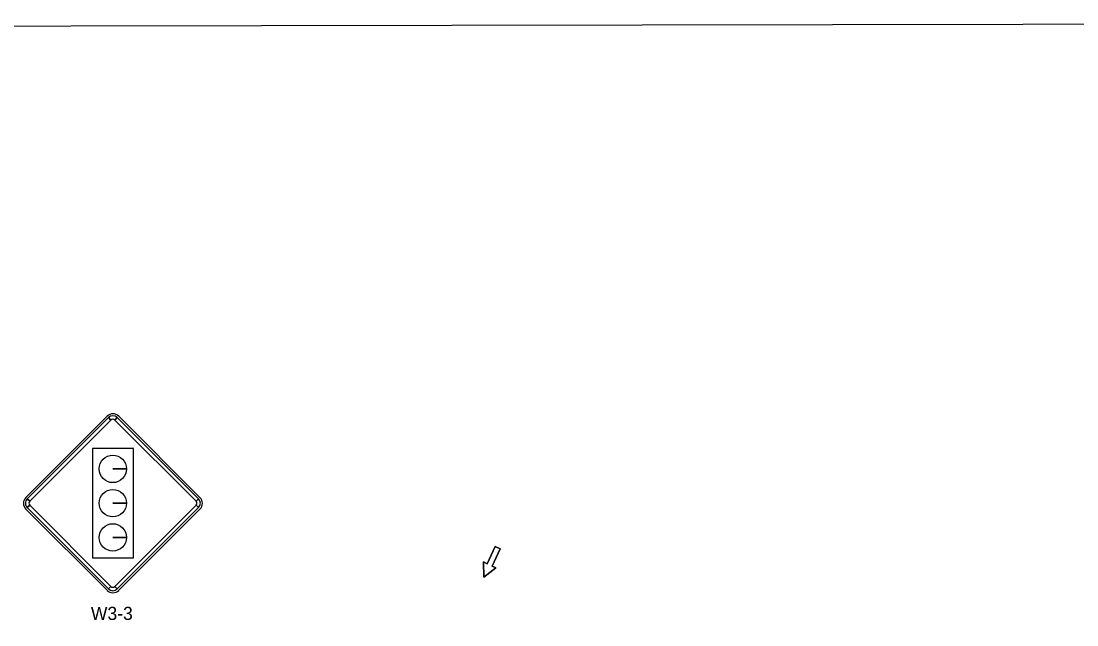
# Model space of a CAD drawing. Extents: x 16513048 to 16518780, y 7009856 to 7010869.
# Drawn here: x 16515285.9 to 16515768.8, y 7010593 to 7010869.1 of the extents above; entities that cross this region are included whole.
import ezdxf

# ---------------------------------------------------------------- set-up
doc = ezdxf.new("R2010")
doc.units = 0
for name, color, linetype in [('dsnStdLabel', 7, 'Continuous'), ('Level 2', 7, 'Continuous'), ('Level 5', 7, 'Continuous'), ('NamedBoundary', 7, 'Continuous')]:
    doc.layers.add(name, color=color, linetype=linetype)

msp = doc.modelspace()

# ---------------------------------------------------------------- linework, layer by layer
at = {"layer": 'dsnStdLabel'}
for p, q in [((16515325.26, 7010688.43), (16515288.08, 7010651.26)), ((16515325.92, 7010687.77), (16515327.03, 7010686.66)), ((16515328.8, 7010686.66), (16515329.91, 7010687.77)), ((16515367.75, 7010651.26), (16515330.57, 7010688.43)), ((16515334.13, 7010664.29), (16515327.87, 7010664.29)), ((16515327.87, 7010664.29), (16515334.13, 7010664.29)), ((16515289.85, 7010649.49), (16515288.75, 7010650.59)), ((16515367.08, 7010650.59), (16515365.98, 7010649.49)), ((16515288.08, 7010645.95), (16515325.26, 7010608.77)), ((16515288.75, 7010646.61), (16515289.85, 7010647.72)), ((16515334.13, 7010648.64), (16515327.87, 7010648.64)), ((16515327.87, 7010648.64), (16515334.13, 7010648.64)), ((16515330.57, 7010608.77), (16515367.75, 7010645.95)), ((16515365.98, 7010647.72), (16515367.08, 7010646.61)), ((16515334.13, 7010632.99), (16515327.87, 7010632.99)), ((16515327.87, 7010632.99), (16515334.13, 7010632.99)), ((16515327.03, 7010610.54), (16515325.92, 7010609.43)), ((16515329.91, 7010609.43), (16515328.8, 7010610.54))]:
    msp.add_line(p, q, dxfattribs=at)
for points in [[(16515325.92, 7010687.77), (16515288.75, 7010650.59), (16515289.85, 7010649.49), (16515327.03, 7010686.66), (16515325.92, 7010687.77)], [(16515367.08, 7010650.59), (16515329.91, 7010687.77), (16515328.8, 7010686.66), (16515365.98, 7010649.49), (16515367.08, 7010650.59)], [(16515337.3, 7010673.61), (16515318.54, 7010673.61), (16515318.54, 7010623.59), (16515337.3, 7010623.59), (16515337.3, 7010673.61)], [(16515288.75, 7010646.61), (16515325.92, 7010609.43), (16515327.03, 7010610.54), (16515289.85, 7010647.72), (16515288.75, 7010646.61)], [(16515329.91, 7010609.43), (16515367.08, 7010646.61), (16515365.98, 7010647.72), (16515328.8, 7010610.54), (16515329.91, 7010609.43)]]:
    msp.add_lwpolyline(points, close=True, dxfattribs=at)
for centre in [(16515327.87, 7010664.29), (16515327.87, 7010648.64), (16515327.87, 7010632.99)]:
    msp.add_circle(centre, 6.26, dxfattribs=at)
for centre, radius, start, end in [((16515327.92, 7010685.78), 3.76, 45, 134.9997), ((16515327.92, 7010685.78), 2.82, 45, 134.9997), ((16515327.92, 7010685.78), 1.25, 45, 134.9997), ((16515290.74, 7010648.6), 3.76, 134.9997, 225), ((16515290.74, 7010648.6), 2.82, 134.9997, 225), ((16515365.09, 7010648.6), 2.82, 315.0002, 44.9998), ((16515365.09, 7010648.6), 3.76, 315.0002, 44.9998), ((16515290.74, 7010648.6), 1.25, 134.9997, 225), ((16515365.09, 7010648.6), 1.25, 315.0002, 44.9998), ((16515327.92, 7010611.42), 3.76, 225, 315.0002), ((16515327.92, 7010611.42), 2.82, 225, 315.0002), ((16515327.92, 7010611.42), 1.25, 225, 315.0002)]:
    msp.add_arc(centre, radius, start, end, dxfattribs=at)
at = {"layer": 'Level 2'}
msp.add_lwpolyline([(16515502.81, 7010628.88), (16515505.08, 7010627.82), (16515501.4, 7010619.89), (16515503.1, 7010619.1), (16515497.64, 7010614.74), (16515497.43, 7010621.73), (16515499.13, 7010620.94)], close=True, dxfattribs=at)
at = {"layer": 'Level 5'}
msp.add_lwpolyline([(16515499.13, 7010620.94), (16515497.43, 7010621.73), (16515497.64, 7010614.74), (16515503.1, 7010619.1), (16515501.4, 7010619.89), (16515505.08, 7010627.82), (16515502.81, 7010628.88), (16515499.13, 7010620.94)], dxfattribs=at)
at = {"layer": 'NamedBoundary'}
msp.add_lwpolyline([(16515047.4, 7010866.4), (16515049.16, 7009856.4), (16516616.66, 7009859.13), (16516614.9, 7010869.13)], close=True, dxfattribs=at)

# ---------------------------------------------------------------- texts
at = {"layer": 'dsnStdLabel'}
msp.add_text('W3-3', height=6, dxfattribs=at).set_placement((16515317.84, 7010595.21))

doc.saveas('drawing.dxf')
